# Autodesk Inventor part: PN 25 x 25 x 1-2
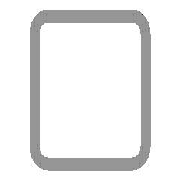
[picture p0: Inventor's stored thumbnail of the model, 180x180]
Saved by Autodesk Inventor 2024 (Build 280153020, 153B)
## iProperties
Company: ATC
Created: 2023-03
Part Number: PN 25 x 25 x 1-2
Material: Stal, miękka
Description: Rury stalowe do zastosowań precyzyjnych -  (Część 5: Rury kwadratowe, spawane, wymiarowane na zimno)
Document SubType Name: Modeling
Standard: PN
Designer: Andrzej Jaskulski
Standards Organization: PN
Language: pl-PL
Size Designation: 25 x 25 x 1
Categories: <MemberInstance><Categories><Category DisplayName="Kształtowniki konstrukcyjne" InternalName="089c4875-fa83-4c05-b084-43b9cc11f5ed" Mnemonic="GRDR"><CategoryPar
Density: 7.85 g/cm^3
Appearance: Częściowo polerowany
Checked By: A.J.
Engr Approved By: Andrzej Jaskulski
Mfg Approved By: Andrzej Jaskulski
Authority: A.J.
Stock Number: 25 x 25 x 1
IsCustomPart: 1
G_L: 544,920 mm
G_W: 25,000 mm
G_H: 25,000 mm
+D691D4FC-71BF-407E-BA48-AD1B38B8DECB+CUTDETAIL1: Połączenie narożnikowe 24,70 deg
+D823DF31-F982-4AB8-9224-3942E330837F+CUTDETAIL2: Połączenie narożnikowe 40,39 deg
_CCFamilyMember: 9
_CCFamilyDisplayName: PN EN 10305-5 (Rury kwadratowe, spawane, wymiarowane na zimno) - Rury stalowe do zastosowań precyzyjnych -  (Część 5: Rury kwadratowe, spawane, wymiarowane na z
_FrameMemberDoc: Frame Member File
_Version: 25.0.0
_GetPNFromCC: 0
Author: Andrzej Jaskulski
Revision Number: 1/24
Title: A.J.: Kurs R2024-MEP
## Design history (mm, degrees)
node "Płaszczyzna początkowa"
node "Płaszczyzna końcowa"
sketch "Szkic"
  geometry: L1 (-12.5, -11)-(-12.5, 11); L2 (-11, 12.5)-(11, 12.5); L3 (12.5, 11)-(12.5, -11); L4 (11, -12.5)-(-11, -12.5); L5 (-11, 11.5)-(11, 11.5); L6 (11.5, 11)-(11.5, -11); L7 (11, -11.5)-(-11, -11.5); L8 (-11.5, -11)-(-11.5, 11); L9 (0, 18.044)-(0, -18.044) reference; L10 (-18.044, 0)-(18.044, 0) reference; A1 r 1.5 centre (-11, -11) between (-12.5, -11) and (-11, -12.5); A2 r 1.5 centre (-11, 11) between (-11, 12.5) and (-12.5, 11); A3 r 1.5 centre (11, 11) between (12.5, 11) and (11, 12.5); A4 r 1.5 centre (11, -11) between (11, -12.5) and (12.5, -11); A5 r 0.5 centre (-11, 11) between (-11, 11.5) and (-11.5, 11); A6 r 0.5 centre (11, 11) between (11.5, 11) and (11, 11.5); A7 r 0.5 centre (11, -11) between (11, -11.5) and (11.5, -11); A8 r 0.5 centre (-11, -11) between (-11.5, -11) and (-11, -11.5)
  constraints: 16 end point, 16 point on circle, 8 centre point, 8 tangent, 4 parallel, 3 equal radius, 2 perpendicular, 7 other
  dimensions: "d7" = 1.5 radius of A1 (= G_IR); "d10" = 25 distance between parallel lines of L2 L4 (= G_H); "d11" = 25 distance between parallel lines of L1 L3 (= G_W); "d12" = 1 distance between parallel lines of L3 L6 (= G_T); "d15" = 12.5 distance between parallel lines of L2 L10 (= 0.5 x d10); "d16" = 12.5 distance between parallel lines of L9 L3 (= 0.5 x d11)
extrude "Bryła" new body sketch "Szkic" stored distance "d3" = 544.91979 (= G_L); taper "d4" = 0 deg
node "Driven Length"
  sketch "Sketch3"
    geometry: L1 (0, 0)-(10, 0) reference
    constraints: 2 end point, 1 horizontal
  workplane "Work Plane3"
node "Płaszczyzna konstrukcyjna4"
feature "Podział1"
node "Płaszczyzna konstrukcyjna5"
feature "Podział2"
body "Solid1"
sketch "Sketch4"
  geometry: L1 (-2, -27.175)-(12, -27.175) reference; L2 (-2, 517.745)-(12, 517.745) reference
  dimensions: "d18" = 544.91979 distance between parallel lines of L1 L2 (derived)
other parameters: "G_W" = 25 [user parameter; used in 1 equation term], "G_H" = 25 [user parameter; used in 1 equation term], "G_T" = 1 [user parameter; used in 1 equation term], "G_IR" = 1.5 [user parameter; used in 1 equation term], "G_L" = 544.91979 (= d18) [user parameter; used in 1 equation term], "G_OFFSET_START" = 27.17503 [user parameter; used in 1 equation term], "G_OFFSET_END" = 14.69144 [user parameter; used in 1 equation term], "d13" = -27.17503 (= -G_OFFSET_START), "d14" = 517.74476 (= G_OFFSET_END + B_L), "B_L" = 503.05333 [user parameter; used in 1 equation term], "d17" = 90 deg
